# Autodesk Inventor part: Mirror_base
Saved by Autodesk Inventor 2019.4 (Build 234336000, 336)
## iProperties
Created: 2019-10
Part Number: Mirror_base
Material: Generic
Document SubType Name: Modeling
Designer: Administrator
Density: 1 g/cm^3
Appearance: Default
Title: Mirror_base
Author: Administrator
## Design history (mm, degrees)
feature "Body1"
body "Solid1"
